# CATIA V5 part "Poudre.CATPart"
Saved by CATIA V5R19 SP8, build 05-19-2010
Part number: Poudre
Bounding box of the stored display mesh (mm): x -4.515 to 4.515, y 0 to 6.8, z -4.515 to 4.515
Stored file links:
  C:\Users\Arthur\Desktop\Catia parts\Poudre.CATPart
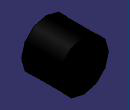
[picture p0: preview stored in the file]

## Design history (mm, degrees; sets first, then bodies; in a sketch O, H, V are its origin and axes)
Set1
  Sketch1 on zx-plane, origin (0, 0, 0), H (-1, 0, 0), V (0, 0, 1)
    circle A1 centre (0, 0) radius 4.515
    radius A1 = 4.515
Body1 (main body)
  Pad1: profile Sketch1, direction (0, 1, 0), length 6.8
